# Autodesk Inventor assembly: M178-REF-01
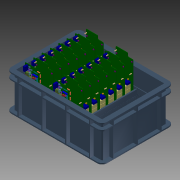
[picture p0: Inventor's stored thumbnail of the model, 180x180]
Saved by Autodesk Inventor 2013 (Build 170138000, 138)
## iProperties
Created: 2004-11
Document SubType Name: Assembly
Designer: Autodesk, Inc.
Manufacturer: Standard
Standards Organization: Custom
Part Number: M178-REF-01
Mass: 3534.78 g
Surface Area: 19733.6 cm^2
Volume: 3534.78 cm^3
Density: 1 g/cm^3
CAGE: 1LJX3
Dept. ID: Product Design
Description #2: ---
Finish #1: ---
Finish #2: ---
Material ID: ---
Project Number: ---
Author: Autodesk, Inc.
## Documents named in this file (4)
- Z:\_DATEN\Test Station\Components\Filled Tote 2.iam
- Z:\_DATEN\Test Station\Components\Standard Tote.iam
- Z:\_DATEN\Test Station\Components\Slots Part 2.ipt
- Z:\_DATEN\Test Station\Components\example2.max.ipt
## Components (19 placed, 3 different names)
1. Standard Tote:1 [sub-assembly] — Angle:2, Flush:1, Mate:1, Mate:2, Mate:3, Mate:4, Mate:6
2. Slots Part 2:1 — Angle:2, Flush:1, Mate:4, Mate:5, Flush:2
3. Slots Part 2:2 — Mate:5, Flush:2, Mate:6
4. Slots Part 2:3
5. Slots Part 2:4
6. example2.max:1 — Mate:1, Mate:2, Mate:3
7. example2.max:2
8. example2.max:3
9. example2.max:4
10. example2.max:5
11. example2.max:6
12. example2.max:7
13. example2.max:8
14. example2.max:9
15. example2.max:10
16. example2.max:11
17. example2.max:12
18. example2.max:13
19. example2.max:14
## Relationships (9: Mate 6, Flush 2, Angle 1)
- Angle:2: Standard Tote:1 ↔ Slots Part 2:1
- Flush:1: Standard Tote:1 ↔ Slots Part 2:1
- Mate:1: Standard Tote:1 ↔ example2.max:1
- Mate:2: Standard Tote:1 ↔ example2.max:1
- Mate:3: Standard Tote:1 ↔ example2.max:1
- Mate:4: Standard Tote:1 ↔ Slots Part 2:1
- Mate:5: Slots Part 2:1 ↔ Slots Part 2:2
- Flush:2: Slots Part 2:1 ↔ Slots Part 2:2
- Mate:6: Standard Tote:1 ↔ Slots Part 2:2
